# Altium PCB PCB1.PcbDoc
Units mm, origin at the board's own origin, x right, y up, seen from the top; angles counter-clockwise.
Board outline 43.18 x 67.82 mm, 2 copper layers (Top Layer, Bottom Layer); 45 components, 24 nets, 112 pads, 8 vias.
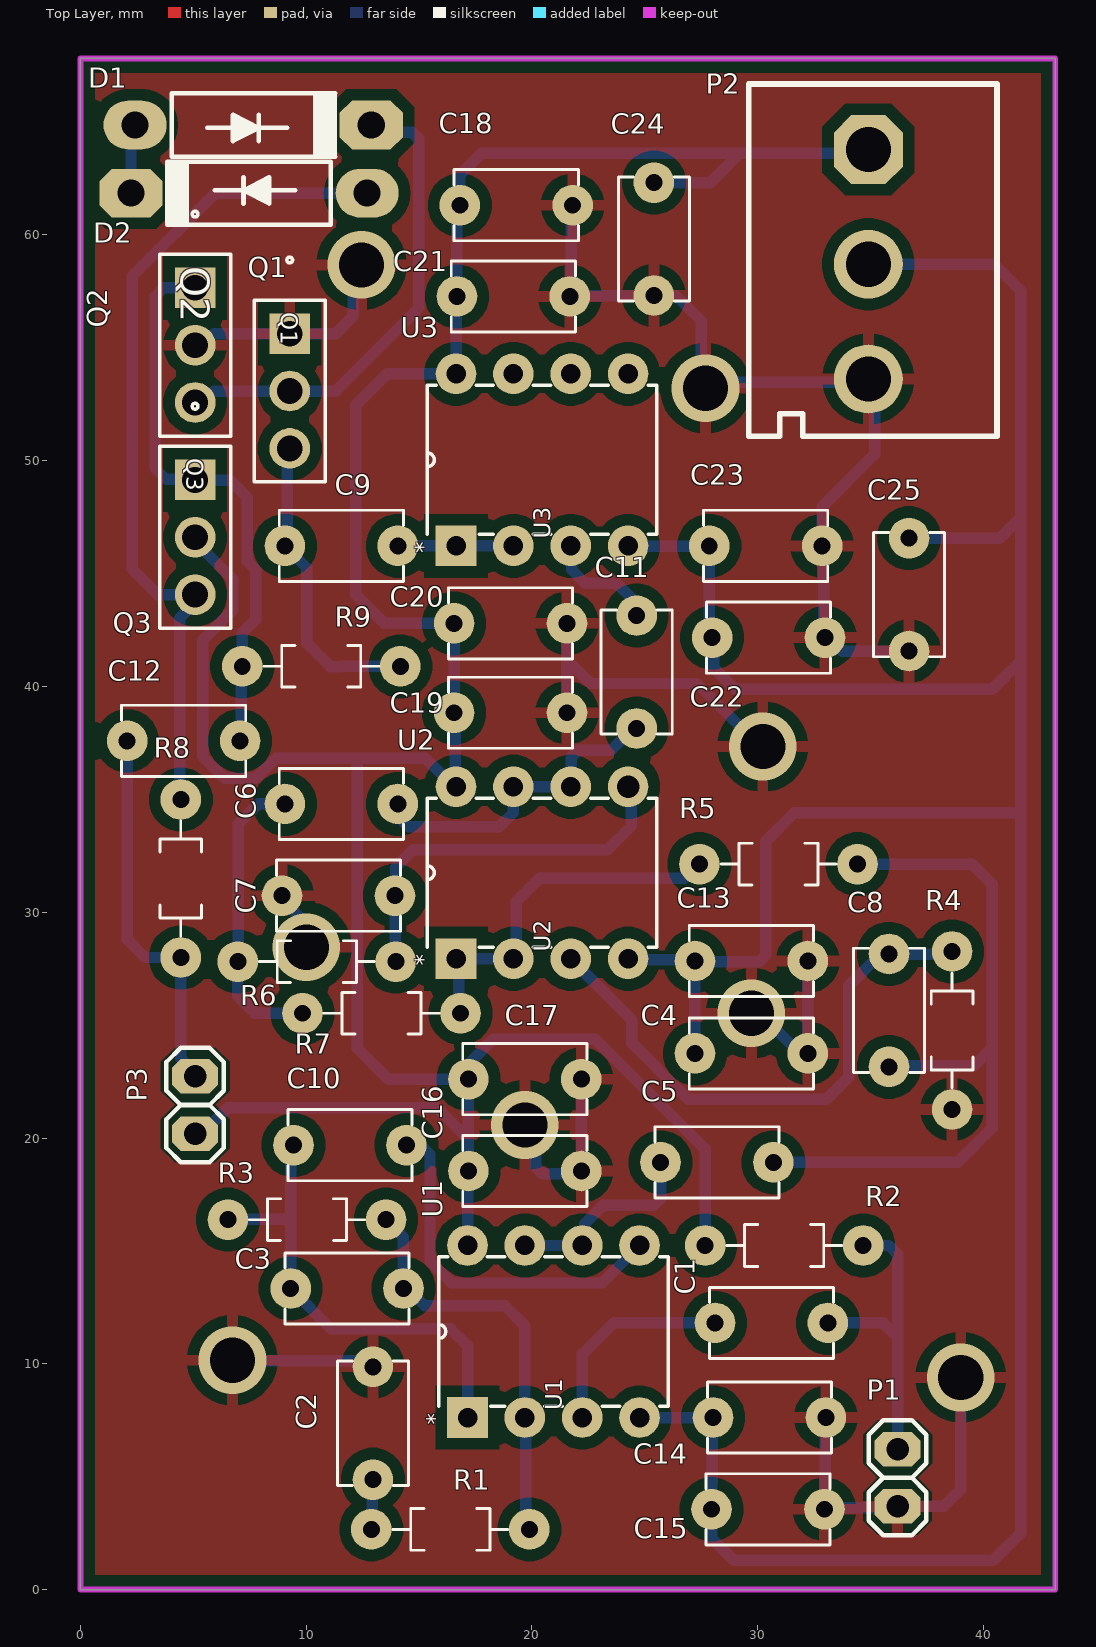
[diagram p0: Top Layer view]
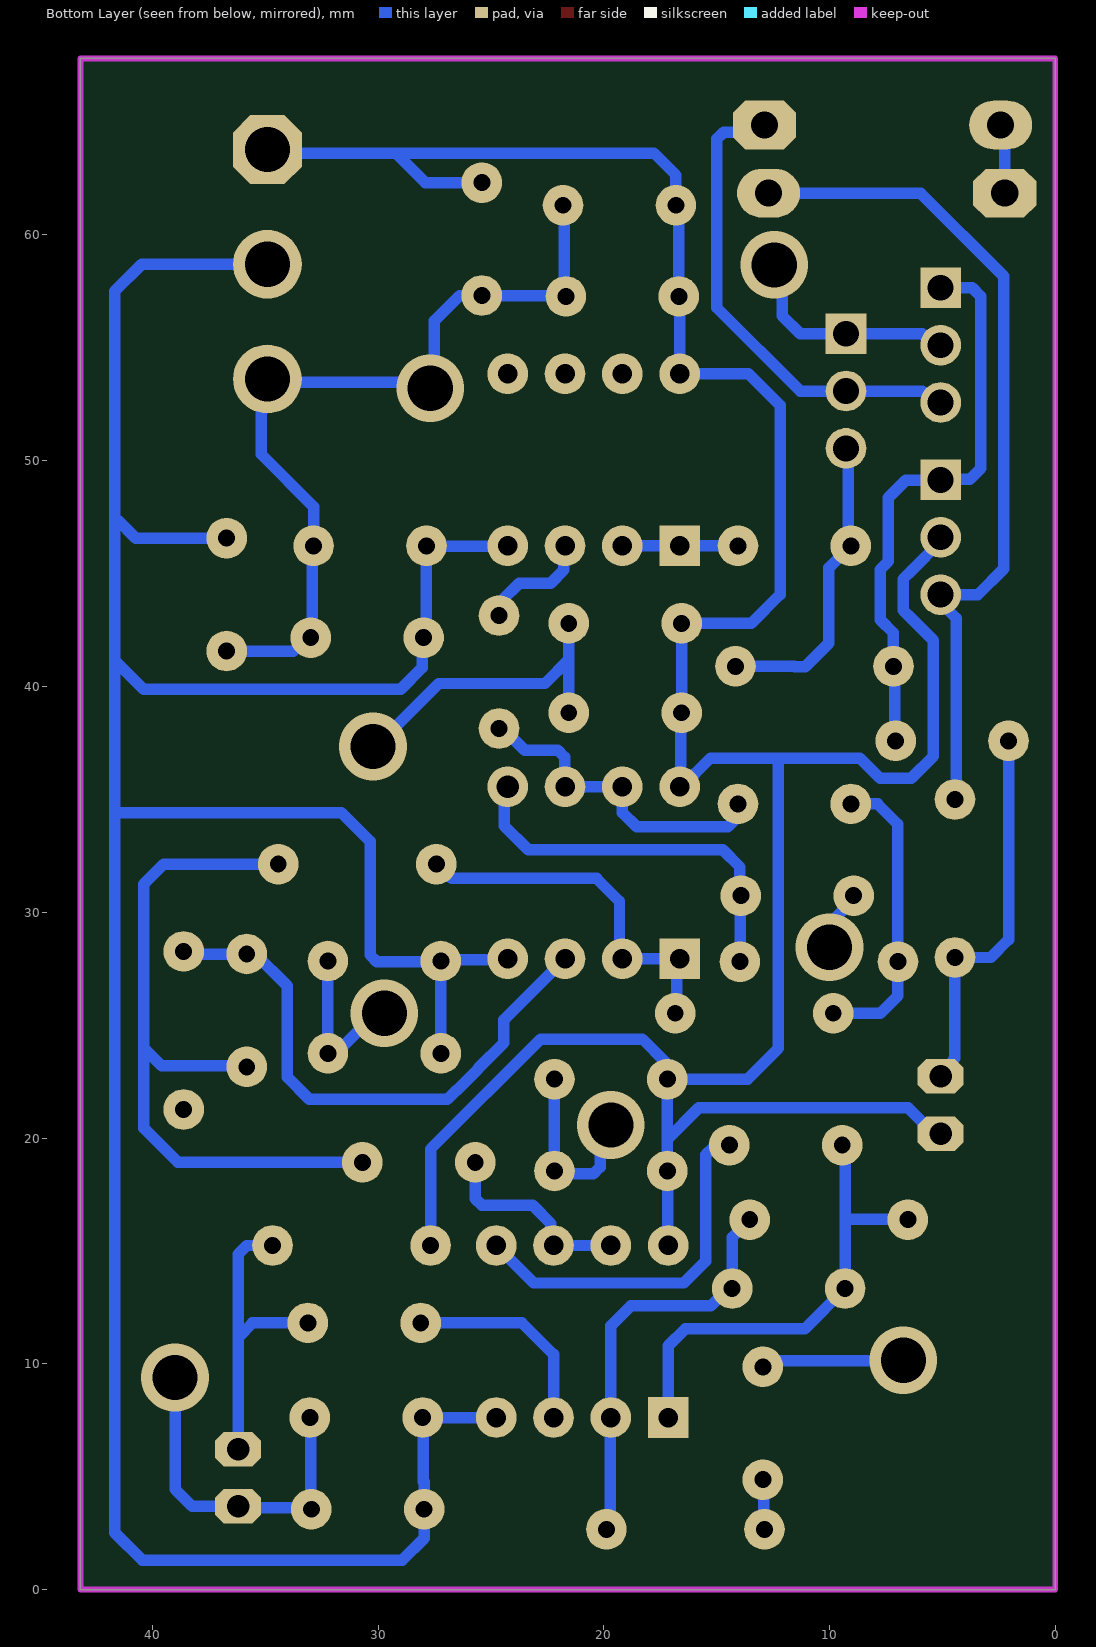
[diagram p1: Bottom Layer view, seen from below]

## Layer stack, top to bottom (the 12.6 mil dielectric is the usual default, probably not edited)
Top Solder: solder mask 0.0102, Solder Resist, Dk 3.5
Top Layer: signal copper 0.0356
Dielectric 1: dielectric 0.32, FR-4, Dk 4.8
Bottom Layer: signal copper 0.0356
Bottom Solder: solder mask 0.0102, Solder Resist, Dk 3.5

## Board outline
0,0 0,67.818 43.18,67.818 43.18,0

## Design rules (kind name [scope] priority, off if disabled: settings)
Clearance Clearance_2 [InNamedPolygon('GND_POUR')] p1: gap=0.5 ignorepadtopadclearanceinfootprint=FALSE
Clearance [All] p2: gap=0.508 ignorepadtopadclearanceinfootprint=FALSE
PolygonConnect PolygonConnect_1 [All] p1: thpad.connectstyle=Relief thpad.reliefconductorwidth=0.5 thpad.reliefentries=4 thpad.polygonreliefangle="90 Angle" thpad.airgapwidth=0.5 smdpad.connectstyle=Relief smdpad.reliefconductorwidth=0.254 smdpad.reliefentries=4 smdpad.polygonreliefangle="90 Angle" smdpad.airgapwidth=0.254 via.connectstyle=Relief via.reliefconductorwidth=0.5 via.reliefentries=4 via.polygonreliefangle="90 Angle" via.airgapwidth=0.5
PolygonConnect [All] p2: connectstyle=Relief reliefconductorwidth=0.254 reliefentries=4 polygonreliefangle="90 Angle" airgapwidth=0.254
RoutingVias [All] p1: holewidth=0.711 width=1.27 viastyle="Through Hole" minholewidth=0.711 minwidth=1.27 maxholewidth=0.711 maxwidth=1.27
SolderMaskExpansion [All] p1: expansion=0.102 istentingtop=FALSE
SupplyNets "Schematic Supply Nets_2" [InNet('-12')] p1: voltage=0.000
SupplyNets "Schematic Supply Nets_1" [InNet('+12')] p2: voltage=0.000
SupplyNets "Schematic Supply Nets" [InNet('GND')] p3: voltage=0.000
Width [All] p1: maxlimit=0.508 minlimit=0.254 preferedwidth=0.508
30 further rules are at their usual default settings.

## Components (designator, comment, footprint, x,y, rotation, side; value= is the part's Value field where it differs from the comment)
C1 "Capacitor" CAP_RDE5C1H104J2K1H03B 30.607,11.811 r180 top value=10u
C2 "Capacitor" CAP_RDE5C1H104J2K1H03B 12.954,7.366 r270 top value=100u
C3 "Capacitor" CAP_RDE5C1H104J2K1H03B 11.811,13.335 r180 top value=100p
C4 "Capacitor" CAP_RDE5C1H104J2K1H03B 29.718,23.749 r0 top value=1u
C5 "Capacitor" CAP_RDE5C1H104J2K1H03B 28.194,18.923 r0 top value=1u
C6 "Capacitor" CAP_RDE5C1H104J2K1H03B 11.557,34.798 r0 top value=110n
C7 "Capacitor" CAP_RDE5C1H104J2K1H03B 11.43,30.734 r0 top value=56n
C8 "Capacitor" CAP_RDE5C1H104J2K1H03B 35.814,25.654 r90 top value=1u
C9 "Capacitor" CAP_RDE5C1H104J2K1H03B 11.557,46.228 r0 top value=47u
C10 "Capacitor" CAP_RDE5C1H104J2K1H03B 11.938,19.685 r180 top value=1u
C11 "Capacitor" CAP_RDE5C1H104J2K1H03B 24.638,40.64 r270 top value=2.2u
C12 "Capacitor" CAP_RDE5C1H104J2K1H03B 4.572,37.592 r180 top value=220u
C13 "Capacitor" CAP_RDE5C1H104J2K1H03B 29.718,27.838 r0 top value=1u
C14 "Capacitor" CAP_RDE5C1H104J2K1H03B 30.52,7.62 r180 top value=1u
C15 "Capacitor" CAP_RDE5C1H104J2K1H03B 30.455,3.556 r180 top value=1u
C16 "Capacitor" CAP_RDE5C1H104J2K1H03B 19.685,18.542 r180 top value=1u
C17 "Capacitor" CAP_RDE5C1H104J2K1H03B 19.685,22.606 r180 top value=1u
C18 "Capacitor" CAP_RDE5C1H104J2K1H03B 19.304,61.316 r180 top value=1u
C19 "Capacitor" CAP_RDE5C1H104J2K1H03B 19.05,38.837 r180 top value=1u
C20 "Capacitor" CAP_RDE5C1H104J2K1H03B 19.05,42.799 r180 top value=1u
C21 "Capacitor" CAP_RDE5C1H104J2K1H03B 19.177,57.277 r180 top value=1u
C22 "Capacitor" CAP_RDE5C1H104J2K1H03B 30.48,42.164 r180 top value=1u
C23 "Capacitor" CAP_RDE5C1H104J2K1H03B 30.353,46.228 r180 top value=1u
C24 "Capacitor" CAP_RDE5C1H104J2K1H03B 25.4,59.817 r270 top value=1u
C25 "Capacitor" CAP_RDE5C1H104J2K1H03B 36.703,44.069 r90 top value=1u
D1 "1N4007" My_DO41 7.62,64.77 r180 top
D2 "1N4007" My_DO41 7.5,61.951 r0 top
P1 "Header 2" My_1X02 36.195,3.683 r270 top
P2 "Header 3" My_CN3 34.912,58.661 r270 top
P3 "Header 2" My_1X02 5.08,20.193 r270 top
Q1 "BD139G" SOT-32_STM 9.271,55.626 r270 top
Q2 "BD14016STU" SOT-32_STM 5.08,57.658 r270 top
Q3 "BD139G" SOT-32_STM 5.08,49.149 r270 top
R1 "Resistor" RESAD700W45L350D185 16.383,2.667 r0 top value=1K
R2 "Resistor" RESAD700W45L350D185 31.171,15.24 r0 top value=10K
R3 "Resistor" RESAD700W45L350D185 10.033,16.383 r180 top value=100K
R4 "Resistor" RESAD700W45L350D185 38.608,24.765 r270 top value=22K
R5 "Resistor" RESAD700W45L350D185 30.917,32.131 r180 top value=10K
R6 "Resistor" RESAD700W45L350D185 10.47,27.813 r0 top value=10K
R7 "Resistor" RESAD700W45L350D185 13.335,25.527 r180 top value=10K
R8 "Resistor" RESAD700W45L350D185 4.445,31.496 r90 top value=1.2K
R9 "Resistor" RESAD700W45L350D185 10.668,40.894 r180 top value=100K
U1 "NE5532ANG" P8#1 24.765,15.24 r90 top
U2 "NE5532ANG" P8#2 24.257,35.56 r90 top
U3 "NE5532ANG" P8#1 24.257,53.848 r90 top

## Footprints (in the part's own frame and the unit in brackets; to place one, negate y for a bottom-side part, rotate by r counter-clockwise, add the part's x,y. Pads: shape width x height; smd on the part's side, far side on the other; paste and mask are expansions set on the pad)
CAP_RDE5C1H104J2K1H03B [mm]
  round 1.8 hole 0.75: 1(-2.5,0) 2(2.5,0)
  silkscreen extent -2.75,-1.58 2.75,1.58
My_1X02 [mil]
  oct 60x80 hole 39.37: 1(-100,0) 2(0,0)
  silkscreen extent -150,-50 50,50, body extent -150,-51 46,47, height 323
My_CN3 [mil]
  oct 120x120 hole 78.74: 1(-201.5,-0.5)
  round 120 hole 78.74: 2(-1.5,-0.5) 3(198.5,-0.5)
  silkscreen extent -316,-209 299,224, body extent -320,-214 302,227, height 721
My_DO41 [mil]
  oval 110x85 hole 47.24: A(204.71,-4)
  oct 110x85 hole 47.24: K(-207.1,-4)
  silkscreen extent -148,-59 141,51, body extent -228,-53 228,45, height 104
P8#1 [mm]
  rect 1.8x1.8 hole 0.864 paste-2539.97 mask-0.686: 1(-7.62,7.62)
  round 1.8 hole 0.864 paste-2539.97 mask-0.686: 2(-7.62,5.08) 3(-7.62,2.54) 4(-7.62,0) 5(0,0) 6(0,2.54) 7(0,5.08) 8(0,7.62)
  silkscreen extent -7.11,-1.27 -0.51,8.89, body extent -7.75,-1.27 0.38,8.89, height 5.21
P8#2 [mm]
  rect 1.8x1.8 hole 0.864 paste-2539.97 mask-0.686: 1(-7.62,7.62)
  round 1.8 hole 0.864 paste-2539.97 mask-0.686: 2(-7.62,5.08) 3(-7.62,2.54) 4(-7.62,0) 6(0,2.54) 7(0,5.08) 8(0,7.62)
  round 1.8 hole 1 paste-2539.97 mask-0.686: 5(0,0)
  silkscreen extent -7.11,-1.27 -0.51,8.89, body extent -7.75,-1.27 0.38,8.89, height 5.21
RESAD700W45L350D185 [mm]
  round 1.8 hole 0.75: 1(-3.5,0) 2(3.5,0)
  silkscreen extent -2.55,-0.92 2.55,0.92, body extent -3.72,-0.92 3.72,0.92, height 1.84
SOT-32_STM [mm]
  rect 1.8x1.8 hole 1.143 paste-2539.97 mask+0: 1(0,0)
  round 1.8 hole 1.143 paste-2539.97 mask+0: 2(2.54,0) 3(5.08,0)
  silkscreen extent -3.39,-1.57 6.57,1.57, body extent -1.36,-1.45 6.44,1.45, height 8.89

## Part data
D1 D2: "1 Amp Diode", ASiD Part Number=1n4007-AS
P1 P3: "Header, 2-Pin", ASiD Part Number="Header 2-AS"
P2: "Header, 3-Pin", ASiD Part Number="Header 3-AS"
Q1 Q2 Q3 U1 U2 U3: "No Description Available", Manufacturer_Name=onsemi

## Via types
v1: diameter 3, hole 2, Top Layer to Bottom Layer, 8 vias

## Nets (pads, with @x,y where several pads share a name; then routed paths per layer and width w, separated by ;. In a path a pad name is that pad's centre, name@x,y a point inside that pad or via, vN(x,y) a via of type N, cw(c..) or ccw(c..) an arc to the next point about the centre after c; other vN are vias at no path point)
+12: C16.2 C17.2 C18.2 C19.2 C20.2 C21.2 C24.1 P2.1 P3.2 Q3.2 R2.1 U1.8 U2.8 U3.8 | length 137.2
  Bottom Layer w0.508: Q3.2 5.08,46.419 6.379,45.12 6.742,44.757 6.742,43.381 6.379,43.018 5.41,42.049 5.41,36.904 6.384,35.93 7.76,35.93 8.66,36.83 12.268,36.83 15.273,36.83 16.543,35.56 U2.8 ; P3.2@5.378,20.193 6.521,21.336 8.739,21.336 8.75,21.347 15.126,21.347 15.137,21.336 15.788,21.336 17.185,19.939 ; 12.268,36.779 12.268,23.971 13.633,22.606 C17.2 ; U2.8@16.593,35.604 16.593,38.793 C19.2 C20.2 13.462,42.799 12.192,44.069 12.192,52.451 13.589,53.848 U3.8 16.637,57.237 C21.2 16.677,61.189 C18.2 16.804,62.651 17.78,63.627 29.21,63.627 ; U1.8 17.165,15.26 17.165,18.522 C16.2 17.185,19.939 ; C24.1 27.9,62.317 29.21,63.627 ; R2.1 27.671,19.509 22.796,24.384 18.288,24.384 17.285,23.381 17.285,22.706 C17.2 ; P2.1 34.747,63.627 29.21,63.627 ; 17.185,19.939 C17.2
-12: C4.1 C13.1 C14.2 C15.2 C22.2 C23.2 C25.2 P2.2 U1.4 U2.4 U3.4 | length 141.6
  Bottom Layer w0.508: U2.4 24.308,27.889 27.167,27.889 C13.1 ; U3.4 24.27,46.215 C23.2@27.853,46.215 ; U1.4 C14.2 27.987,7.587 27.987,4.779 27.955,4.779 C15.2 27.955,2.271 28.932,1.294 40.434,1.294 41.656,2.516 41.656,34.544 ; C4.1 C13.1 ; C23.2 C23.2@27.853,46.215 ; P2.2 40.469,58.699 41.656,57.513 41.656,47.371 41.656,41.148 ; C25.2 40.727,46.569 41.529,47.371 ; C13.1 27.243,27.813 30.055,27.813 30.353,28.111 30.353,33.147 31.623,34.417 41.529,34.417 41.656,34.544 ; C23.2@27.853,46.215 27.853,42.291 28.047,42.097 28.047,40.827 28.996,39.878 40.386,39.878 41.656,41.148 ; 41.656,34.544 41.656,41.148
GND: C2.1 C4.2 C7.1 C13.2 C14.1 C15.1 C16.1 C17.1 C18.1 C19.1 C20.1 C21.1 C22.1 C23.1 C24.2 C25.1 P1.2 P2.3 Q1.1 Q2.2 R4.2 | length 101.9
  Bottom Layer w0.254: P2.3@34.849,53.67 P2.3
  Bottom Layer w0.508: Q2.2 5.389,55.118 5.897,55.626 Q1.1 11.303,55.626 12.089,56.412 12.089,58.317 v1(12.446,58.674) ; v1(6.731,10.16) 6.751,10.14 12.934,10.14 C2.1@12.954,10.12 ; C7.1 8.93,30.56 9.683,29.807 9.683,28.771 v1(10.006,28.448) ; v1(19.685,20.574) 20.162,20.097 20.162,18.713 20.459,18.415 20.967,18.415 20.972,18.419 22.062,18.419 C16.1 C17.1 ; C19.1 21.55,41.188 ; C20.1 21.55,41.188 ; C21.1 C21.1@21.697,57.297 ; C18.1 21.741,61.252 21.741,57.34 C21.1@21.697,57.297 ; C24.2 26.376,57.317 27.504,56.189 27.504,53.395 v1(27.686,53.213) 27.953,53.48 34.658,53.48 P2.3@34.849,53.67 ; C24.2@25.41,57.307 25.39,57.307 25.38,57.297 C21.1@21.697,57.297 ; v1(29.718,25.527) 30.09,25.527 31.868,23.749 C4.2 C13.2 C13.2@32.302,27.922 ; v1@30.162,37.274 27.305,40.132 22.606,40.132 21.55,41.188 ; C23.1@32.766,46.315 C23.1 ; C22.1@32.897,42.081 C22.1 ; C15.1 C15.1@32.987,3.589 ; C14.1 32.987,7.587 C15.1@32.987,3.589 ; P2.3 35.179,53.34 35.179,50.292 32.853,47.966 C23.1 ; C25.1 33.749,41.569 33.154,42.164 C22.1 ; v1(38.989,9.398) 38.989,4.445 38.227,3.683 P1.2 36.131,3.619 33.018,3.619 C15.1@32.987,3.589 ; C23.1 32.917,46.164 32.917,42.227 C22.1
  other v1: 30.226,37.338
NetC1_1: C1.1 P1.1 R2.2 | length 13.7
  Bottom Layer w0.508: C1.1 35.56,11.811 36.195,11.176 ; R2.2 35.814,15.24 36.195,14.859 36.195,11.176 ; P1.1 36.195,11.176
NetC1_2: C1.2 U1.3 | length 9.3
  Bottom Layer w0.508: U1.3 22.225,10.414 23.622,11.811 C1.2
NetC2_2: C2.2 R1.1 | length 2.2
  Bottom Layer w0.508: R1.1 12.919,2.703 12.919,4.831 C2.2
NetC3_1: C3.1 R1.2 R3.1 U1.2 | length 18
  Bottom Layer w0.508: R3.1 14.303,15.613 14.303,13.343 14.477,13.343 15.258,12.562 18.807,12.562 19.685,11.684 U1.2 19.72,7.585 19.72,3.211 R1.2@19.756,3.175
NetC3_2: C3.2 C10.2 R3.2 U1.1 | length 21.2
  Bottom Layer w0.508: R3.2@6.533,16.413 9.311,16.413 ; C10.2 9.311,19.558 9.311,16.413 ; U1.1 17.145,10.795 16.394,11.546 11.1,11.546 C3.2 9.311,16.413
NetC5_1: C5.1 U1.6 U1.7 | length 9.2
  Bottom Layer w0.508: U1.7 19.685,15.367 19.812,15.24 U1.6 22.344,15.359 22.344,16.212 23.15,17.018 25.396,17.018 25.694,17.316 C5.1
NetC5_2: C5.2 C8.1 R5.1 | length 32.7
  Bottom Layer w0.508: C5.2 38.862,18.923 40.38,20.441 40.38,23.982 40.38,31.248 39.497,32.131 R5.1 ; C8.1@35.433,23.154 35.474,23.195 39.578,23.195 40.365,23.982
NetC6_1: C6.1 R6.1 R7.2 | length 13.2
  Bottom Layer w0.508: C6.1 7.874,34.798 6.985,33.909 6.985,27.828 R6.1 6.97,26.304 7.747,25.527 R7.2
NetC6_2: C6.2 C11.2 U2.6 U2.7 | length 14.6
  Bottom Layer w0.508: C6.2 14.18,34.675 14.18,34.113 14.511,33.782 18.542,33.782 19.177,34.417 U2.7 U2.6 21.734,35.577 21.734,36.877 22.032,37.175 23.499,37.175 24.464,38.14 C11.2
NetC7_2: C7.2 R6.2 U2.5 | length 17.2
  Bottom Layer w0.508: R6.2 13.95,27.833 13.95,30.714 C7.2 13.97,30.774 13.97,32.004 14.732,32.766 23.346,32.766 24.406,33.826 24.406,35.411 U2.5
NetC8_2: C8.2 R4.1 U2.3 | length 25.5
  Bottom Layer w0.508: U2.3 24.423,25.234 24.423,24.218 25.556,23.085 25.556,23.061 26.53,22.087 26.554,22.087 26.924,21.717 33.043,21.717 34.025,22.699 34.025,26.746 35.433,28.154 35.441,28.146 38.981,28.146 R4.1@38.989,28.138
NetC9_1: C9.1 Q1.3 R9.1 | length 13.7
  Bottom Layer w0.508: Q1.3 9.164,50.439 9.164,46.335 C9.1 10.033,45.252 10.033,41.91 11.071,40.872 11.551,40.872 11.573,40.894 R9.1
NetC9_2: C9.2 U3.1 U3.2 | length 5.1
  Bottom Layer w0.508: C9.2 U3.1 U3.2
NetC10_1: C10.1 U1.5 | length 16.3
  Bottom Layer w0.508: C10.1 14.561,19.562 15.181,19.562 15.483,19.26 15.483,14.552 16.457,13.578 23.103,13.578 U1.5
NetC11_1: C11.1 U3.3 | length 5.1
  Bottom Layer w0.508: U3.3 21.768,46.177 21.768,45.161 22.352,44.577 23.749,44.577 24.515,43.811 24.515,43.263 C11.1
NetC12_1: C12.1 Q2.1 Q3.1 R9.2 | length 25.4
  Bottom Layer w0.508: Q2.1 3.683,57.658 3.302,57.277 3.302,49.657 3.79,49.169 5.06,49.169 5.1,49.129 6.624,49.129 7.395,48.358 7.395,45.541 7.758,45.178 7.758,42.96 7.168,42.37 7.168,41.097 7.12,41.049 7.12,37.64 C12.1
NetC12_2: C12.2 P3.1 R8.1 | length 17
  Bottom Layer w0.508: C12.2 2.072,28.789 2.865,27.996 R8.1 4.445,23.539 4.55,23.433 4.55,23.241 5.058,22.733 P3.1
NetD1_A: D1.A D2.K | length 3.1
  Bottom Layer w0.508: D2.K 2.24,64.691 D1.A
NetD1_K: D1.K Q1.2 Q2.3 | length 21
  Bottom Layer w0.508: Q2.3 5.389,52.578 5.897,53.086 Q1.2 11.303,53.086 14.986,56.769 14.986,64.257 14.688,64.554 13.706,64.554 D1.K@13.388,64.872
NetD2_A: D2.A Q3.3 R8.2 | length 37.5
  Bottom Layer w0.508: R8.2 4.394,35.047 4.394,43.033 5.08,43.719 Q3.3 3.429,44.069 2.286,45.212 2.286,58.166 5.969,61.849 D2.A
NetR5_2: R5.2 R7.1 U2.1 U2.2 | length 16.3
  Bottom Layer w0.508: R7.1@16.764,25.654 16.764,27.813 U2.1 U2.2 19.304,28.067 19.304,30.48 20.32,31.496 26.744,31.496 27.379,32.131 R5.2
pads on no net: U3.5 U3.6 U3.7

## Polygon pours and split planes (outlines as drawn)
GND on Top Layer "GND_L01_P000" (solid, pour order 0): 0,0 0,67.818 43.18,67.818 43.18,0

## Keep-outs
Keep-Out Layer:
  the board outline again, w0.254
